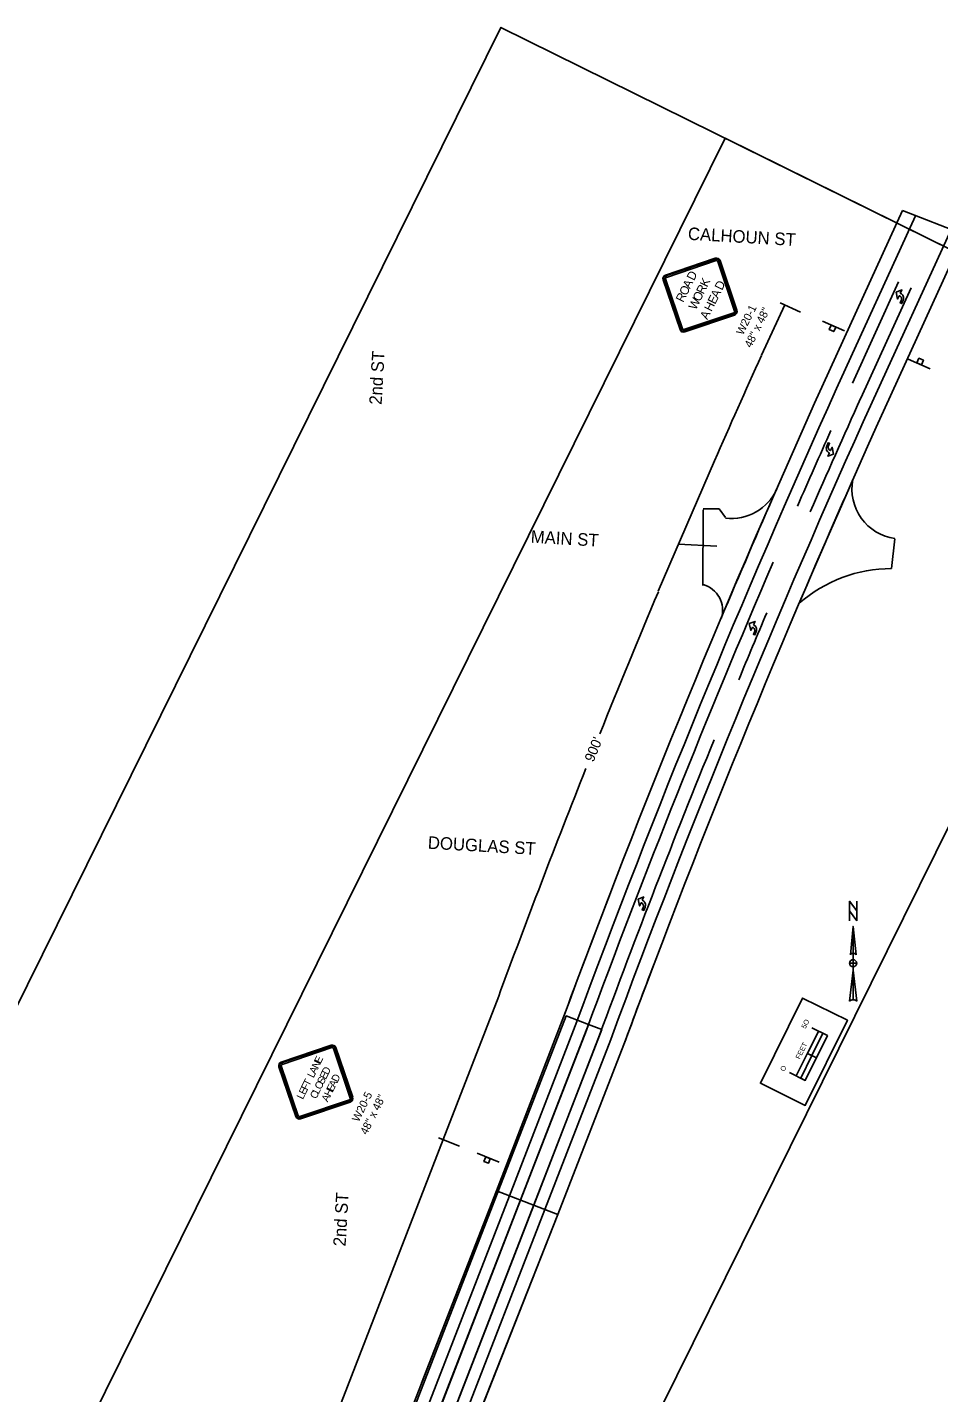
# Model space of a CAD drawing. Extents: x 14104283 to 14128447, y 8633203 to 8671666.
# Drawn here: x 14119504 to 14120414, y 8670301 to 8671666 of the extents above; entities that cross this region are included whole.
import ezdxf

# ---------------------------------------------------------------- set-up
doc = ezdxf.new("R2010")
doc.units = 0
for name, color, linetype in [('Cell', 7, 'Continuous'), ('Default', 7, 'Continuous'), ('dsnCellsNorthArrow', 7, 'Continuous'), ('dsnCellsScaleBlock', 7, 'Continuous'), ('dsnNonPlotable', 7, 'Continuous'), ('dsnPaintExistingBrokenLaneLineWhite', 7, 'Continuous'), ('dsnPaintExistingDoubleCenterYellow', 7, 'Continuous'), ('dsnPaintExistingEdgeLineRightWhite', 7, 'Continuous'), ('dsnPaintExistingLaneLineWhite', 7, 'Continuous'), ('dsnPaintExistingNoPassingYellow', 7, 'Continuous'), ('dsnShadingPaved', 7, 'Continuous'), ('dsnStdLabel', 7, 'Continuous'), ('dsnTextOverlapEven', 7, 'Continuous'), ('dsnTextOverlapOdd', 7, 'Continuous')]:
    doc.layers.add(name, color=color, linetype=linetype)

msp = doc.modelspace()

# ---------------------------------------------------------------- linework, layer by layer
at = {"layer": 'Cell'}
for p, q in [((14120190.9, 8671434.9), (14120141.2, 8671418.1)), ((14120191.2, 8671434), (14120191.7, 8671432.6)), ((14120193.3, 8671431.8), (14120194.8, 8671432.3)), ((14120212.5, 8671382.9), (14120195.7, 8671432.6)), ((14120142, 8671415.7), (14120141.5, 8671417.2)), ((14120138.8, 8671413.4), (14120155.7, 8671363.6)), ((14120139.7, 8671413.7), (14120141.2, 8671414.2)), ((14120374.9, 8671397.3), (14120374.6, 8671397.4)), ((14120375.7, 8671399.8), (14120375.9, 8671399.7)), ((14120160.4, 8671361.3), (14120210.1, 8671378.1)), ((14120209.3, 8671380.5), (14120209.8, 8671379)), ((14120211.6, 8671382.6), (14120210.1, 8671382.1)), ((14120158, 8671364.4), (14120156.5, 8671363.9)), ((14120160.1, 8671362.2), (14120159.6, 8671363.6)), ((14120298.1, 8671372), (14120320.1, 8671362.2)), ((14120405.4, 8671324.5), (14120383.4, 8671334.2)), ((14120305, 8671240.3), (14120304.8, 8671240.4)), ((14120305.8, 8671242.8), (14120306.1, 8671242.7)), ((14120228.2, 8671066.1), (14120227.9, 8671066.2)), ((14120229, 8671068.6), (14120229.2, 8671068.5)), ((14120117.1, 8670790.7), (14120116.9, 8670790.8)), ((14120118, 8670793.2), (14120118.1, 8670793.1)), ((14119807.1, 8670648.4), (14119757.4, 8670631.5)), ((14119807.4, 8670647.5), (14119807.9, 8670646)), ((14119809.5, 8670645.2), (14119811, 8670645.7)), ((14119828.7, 8670596.3), (14119811.9, 8670646)), ((14119755, 8670626.8), (14119771.8, 8670577.1)), ((14119755.9, 8670627.1), (14119757.4, 8670627.6)), ((14119758.2, 8670629.2), (14119757.7, 8670630.7)), ((14119776.6, 8670574.7), (14119826.3, 8670591.5)), ((14119825.5, 8670593.9), (14119826, 8670592.4)), ((14119827.8, 8670596), (14119826.3, 8670595.5)), ((14119774.2, 8670577.9), (14119772.7, 8670577.4)), ((14119776.3, 8670575.6), (14119775.8, 8670577.1)), ((14119952.9, 8670540.4), (14119975.1, 8670531.4))]:
    msp.add_line(p, q, dxfattribs=at)
for points in [[(14120191.2, 8671434), (14120141.5, 8671417.2), (14120142, 8671415.7), (14120191.7, 8671432.6), (14120191.2, 8671434)], [(14120211.6, 8671382.6), (14120194.8, 8671432.3), (14120193.3, 8671431.8), (14120210.1, 8671382.1), (14120211.6, 8671382.6)], [(14120139.7, 8671413.7), (14120156.5, 8671363.9), (14120158, 8671364.4), (14120141.2, 8671414.2), (14120139.7, 8671413.7)], [(14120160.1, 8671362.2), (14120209.8, 8671379), (14120209.3, 8671380.5), (14120159.6, 8671363.6), (14120160.1, 8671362.2)], [(14120311.2, 8671366.1), (14120306.7, 8671368.1), (14120304.7, 8671363.6), (14120309.2, 8671361.6)], [(14120392.3, 8671330.4), (14120396.8, 8671328.4), (14120398.7, 8671332.9), (14120394.3, 8671334.9)], [(14119807.4, 8670647.5), (14119757.7, 8670630.7), (14119758.2, 8670629.2), (14119807.9, 8670646), (14119807.4, 8670647.5)], [(14119827.8, 8670596), (14119811, 8670645.7), (14119809.5, 8670645.2), (14119826.3, 8670595.5), (14119827.8, 8670596)], [(14119755.9, 8670627.1), (14119772.7, 8670577.4), (14119774.2, 8670577.9), (14119757.4, 8670627.6), (14119755.9, 8670627.1)], [(14119776.3, 8670575.6), (14119826, 8670592.4), (14119825.5, 8670593.9), (14119775.8, 8670577.1), (14119776.3, 8670575.6)], [(14119966.1, 8670534.9), (14119961.6, 8670536.7), (14119959.8, 8670532.2), (14119964.3, 8670530.4)]]:
    msp.add_lwpolyline(points, close=True, dxfattribs=at)
for points in [[(14120371.5, 8671401), (14120377.3, 8671403.2), (14120375.7, 8671399.8)], [(14120371.5, 8671401), (14120377.3, 8671403.2), (14120375.7, 8671399.8)], [(14120374.6, 8671397.4), (14120373, 8671394.1), (14120371.5, 8671401)], [(14120374.6, 8671397.4), (14120373, 8671394.1), (14120371.5, 8671401)], [(14120374.9, 8671397.3), (14120374.6, 8671397.4)], [(14120375.7, 8671399.8), (14120375.9, 8671399.7)], [(14120378.5, 8671393), (14120377.1, 8671389.6), (14120375.7, 8671390.2), (14120376.7, 8671392.6)], [(14120378.5, 8671393), (14120377.1, 8671389.6), (14120375.7, 8671390.2), (14120376.7, 8671392.6)], [(14120311.2, 8671366.1), (14120306.7, 8671368.1), (14120304.7, 8671363.6), (14120309.2, 8671361.6), (14120311.2, 8671366.1)], [(14120392.3, 8671330.4), (14120396.8, 8671328.4), (14120398.7, 8671332.9), (14120394.3, 8671334.9), (14120392.3, 8671330.4)], [(14120302.2, 8671247.1), (14120303.6, 8671250.5), (14120305, 8671250), (14120304, 8671247.5)], [(14120302.2, 8671247.1), (14120303.6, 8671250.5), (14120305, 8671250), (14120304, 8671247.5)], [(14120309.1, 8671239.2), (14120303.4, 8671237), (14120305, 8671240.3)], [(14120309.1, 8671239.2), (14120303.4, 8671237), (14120305, 8671240.3)], [(14120305, 8671240.3), (14120304.8, 8671240.4)], [(14120305.8, 8671242.8), (14120306.1, 8671242.7)], [(14120306.1, 8671242.7), (14120307.7, 8671246), (14120309.1, 8671239.2)], [(14120306.1, 8671242.7), (14120307.7, 8671246), (14120309.1, 8671239.2)], [(14120224.8, 8671069.7), (14120230.6, 8671071.9), (14120229, 8671068.6)], [(14120224.8, 8671069.7), (14120230.6, 8671071.9), (14120229, 8671068.6)], [(14120227.9, 8671066.2), (14120226.3, 8671062.9), (14120224.8, 8671069.7)], [(14120227.9, 8671066.2), (14120226.3, 8671062.9), (14120224.8, 8671069.7)], [(14120228.2, 8671066.1), (14120227.9, 8671066.2)], [(14120229, 8671068.6), (14120229.2, 8671068.5)], [(14120231.8, 8671061.8), (14120230.4, 8671058.4), (14120229, 8671058.9), (14120230, 8671061.4)], [(14120231.8, 8671061.8), (14120230.4, 8671058.4), (14120229, 8671058.9), (14120230, 8671061.4)], [(14120113.8, 8670794.4), (14120119.5, 8670796.6), (14120118, 8670793.2)], [(14120113.8, 8670794.4), (14120119.5, 8670796.6), (14120118, 8670793.2)], [(14120116.9, 8670790.8), (14120115.3, 8670787.5), (14120113.8, 8670794.4)], [(14120116.9, 8670790.8), (14120115.3, 8670787.5), (14120113.8, 8670794.4)], [(14120117.1, 8670790.7), (14120116.9, 8670790.8)], [(14120118, 8670793.2), (14120118.1, 8670793.1)], [(14120120.8, 8670786.4), (14120119.4, 8670783), (14120118, 8670783.6), (14120119, 8670786)], [(14120120.8, 8670786.4), (14120119.4, 8670783), (14120118, 8670783.6), (14120119, 8670786)], [(14119966.1, 8670534.9), (14119961.6, 8670536.7), (14119959.8, 8670532.2), (14119964.3, 8670530.4), (14119966.1, 8670534.9)]]:
    msp.add_lwpolyline(points, dxfattribs=at)
for centre, radius, start, end in [((14120192.1, 8671431.4), 3.75, 18.6913, 108.691), ((14120192.1, 8671431.4), 2.81, 18.6913, 108.691), ((14120192.1, 8671431.4), 1.25, 18.6913, 108.691), ((14120142.4, 8671414.6), 3.75, 108.6912, 198.6909), ((14120142.4, 8671414.6), 2.81, 108.6912, 198.6909), ((14120142.4, 8671414.6), 1.25, 108.6912, 198.6909), ((14120208.9, 8671381.7), 1.25, 288.6911, 18.6913), ((14120208.9, 8671381.7), 2.81, 288.6911, 18.6913), ((14120208.9, 8671381.7), 3.75, 288.6911, 18.6913), ((14120159.2, 8671364.8), 3.75, 198.6909, 288.6911), ((14120159.2, 8671364.8), 2.81, 198.6909, 288.6911), ((14120159.2, 8671364.8), 1.25, 198.6909, 288.6911), ((14119808.3, 8670644.8), 3.75, 18.6913, 108.691), ((14119808.3, 8670644.8), 2.81, 18.6913, 108.691), ((14119808.3, 8670644.8), 1.25, 18.6913, 108.691), ((14119758.6, 8670628), 3.75, 108.6912, 198.6909), ((14119758.6, 8670628), 2.81, 108.6912, 198.6909), ((14119758.6, 8670628), 1.25, 108.6912, 198.6909), ((14119825.1, 8670595.1), 1.25, 288.6911, 18.6913), ((14119825.1, 8670595.1), 2.81, 288.6911, 18.6913), ((14119825.1, 8670595.1), 3.75, 288.6911, 18.6913), ((14119775.4, 8670578.3), 3.75, 198.6909, 288.6911), ((14119775.4, 8670578.3), 2.81, 198.6909, 288.6911), ((14119775.4, 8670578.3), 1.25, 198.6909, 288.6911)]:
    msp.add_arc(centre, radius, start, end, dxfattribs=at)
for centre, major_axis in [((14120373.5, 8671393.9), (-1.4, -3.4)), ((14120373.5, 8671393.9), (-1.4, -3.4)), ((14120373.9, 8671394.9), (-2, -4.86)), ((14120373.9, 8671394.9), (-2, -4.86)), ((14120306.8, 8671245.2), (2, 4.86)), ((14120306.8, 8671245.2), (2, 4.86)), ((14120307.2, 8671246.2), (1.4, 3.4)), ((14120307.2, 8671246.2), (1.4, 3.4)), ((14120226.8, 8671062.7), (-1.4, -3.4)), ((14120226.8, 8671062.7), (-1.4, -3.4)), ((14120227.2, 8671063.6), (-2, -4.86)), ((14120227.2, 8671063.6), (-2, -4.86)), ((14120115.7, 8670787.3), (-1.4, -3.4)), ((14120115.7, 8670787.3), (-1.4, -3.4)), ((14120116.1, 8670788.3), (-2, -4.86)), ((14120116.1, 8670788.3), (-2, -4.86))]:
    msp.add_ellipse(centre, major_axis=major_axis, ratio=0.9474, start_param=1.570796, end_param=3.141593, dxfattribs=at)
at = {"layer": 'Default'}
for p, q in [((14120299, 8671309.7), (14120377.9, 8671482.5)), ((14120377.9, 8671482.5), (14120439.4, 8671458.6)), ((14120439.4, 8671458.6), (14120360.6, 8671285.8)), ((14120194.8, 8671184.3), (14120178.7, 8671184.3)), ((14120194.8, 8671184.3), (14120178.7, 8671184.3)), ((14120201.1, 8671175.8), (14120194.8, 8671184.3)), ((14120201.1, 8671175.8), (14120194.8, 8671184.3)), ((14120178.7, 8671183.5), (14120178.6, 8671107.9)), ((14120178.7, 8671183.5), (14120178.6, 8671107.9)), ((14120370.3, 8671154.6), (14120366.9, 8671124.9)), ((14120370.3, 8671154.6), (14120366.9, 8671124.9)), ((14119972.2, 8670502.9), (14120038.1, 8670672.9)), ((14120099.6, 8670649), (14120033.7, 8670479.1)), ((14120033.7, 8670479.1), (14119972.2, 8670502.9))]:
    msp.add_line(p, q, dxfattribs=at)
msp.add_lwpolyline([(14119861.3, 8670216.9), (14119921, 8670193.8), (14120033.7, 8670479.1), (14119972.2, 8670502.9)], close=True, dxfattribs=at)
for centre, radius, start, end in [((14129121.8, 8667322.2), 9682.1, 155.67905, 159.75253), ((14129183.4, 8667298.3), 9682.1, 155.67905, 159.75253), ((14129183.4, 8667298.3), 9682.1, 156.14717, 156.94403), ((14129183.4, 8667298.3), 9682.1, 156.14717, 156.94403), ((14120377.6, 8671204.3), 50.2, 169.2669, 261.6204), ((14120377.6, 8671204.3), 50.2, 169.2669, 261.6204), ((14129121.8, 8667321.8), 9682.1, 156.35706, 157.19061), ((14129121.8, 8667321.8), 9682.1, 156.35706, 157.19061), ((14120206.8, 8671224.6), 49.9, 263.4387, 336.3571), ((14120206.8, 8671224.6), 49.9, 263.4387, 336.3571), ((14120367.2, 8670984.5), 140.3, 90.1123, 131.2245), ((14120367.2, 8670984.5), 140.3, 90.1123, 131.2245), ((14120171.7, 8671083.2), 26.5, 342.4439, 74.5077), ((14120171.7, 8671083.2), 26.5, 342.4439, 74.5077)]:
    msp.add_arc(centre, radius, start, end, dxfattribs=at)
at = {"layer": 'dsnCellsNorthArrow'}
for p, q in [((14120328.6, 8670767), (14120331.5, 8670738.8)), ((14120328.6, 8670767), (14120328.6, 8670693.7)), ((14120325.8, 8670738.8), (14120325.8, 8670738.8)), ((14120325.9, 8670739), (14120326.5, 8670739.6)), ((14120325.1, 8670692.3), (14120328.6, 8670723.3)), ((14120328.6, 8670726.8), (14120328.6, 8670726.8))]:
    msp.add_line(p, q, dxfattribs=at)
msp.add_lwpolyline([(14120332.2, 8670772.6), (14120325.1, 8670782.5), (14120325.1, 8670792.3), (14120332.2, 8670782.5)], close=True, dxfattribs=at)
for points in [[(14120325.1, 8670772.6), (14120325.1, 8670792.3), (14120332.2, 8670782.5), (14120332.2, 8670792.3)], [(14120325.8, 8670738.8), (14120328.6, 8670767), (14120328.6, 8670740.2)], [(14120332.2, 8670730.3), (14120328.6, 8670730.3), (14120328.6, 8670733.9)], [(14120328.6, 8670726.8), (14120328.6, 8670730.3), (14120325.1, 8670730.3)], [(14120328.6, 8670693.7), (14120328.6, 8670723.3), (14120332.2, 8670692.3)]]:
    msp.add_lwpolyline(points, dxfattribs=at)
for centre, radius, start, end in [((14120328.6, 8670730.3), 3.52, 90, 180), ((14120328.6, 8670736.7), 3.52, 90.0204, 143.1257), ((14120328.6, 8670736.7), 3.52, 36.8481, 90.0218), ((14120328.6, 8670730.3), 3.52, 0, 90), ((14120328.6, 8670730.3), 3.52, 180, 270), ((14120328.6, 8670730.3), 3.52, 270, 360), ((14120328.6, 8670688.6), 5.1, 89.9894, 133.619), ((14120328.6, 8670688.6), 5.11, 46.4021, 90.0006)]:
    msp.add_arc(centre, radius, start, end, dxfattribs=at)
at = {"layer": 'dsnCellsScaleBlock'}
msp.add_line((14120291.9, 8670635.6), (14120282.9, 8670640.1), dxfattribs=at)
msp.add_line((14120291.9, 8670635.6), (14120282.9, 8670640.1), dxfattribs=at)
for points in [[(14120235.9, 8670610.3), (14120278, 8670695.5), (14120322.8, 8670673.3), (14120280.7, 8670588.2)], [(14120280.7, 8670588.2), (14120235.9, 8670610.3), (14120278, 8670695.5), (14120322.8, 8670673.3)], [(14120287.4, 8670637.9), (14120298.4, 8670660.3), (14120294, 8670662.5), (14120282.9, 8670640.1)], [(14120280.8, 8670613.2), (14120291.9, 8670635.6), (14120287.4, 8670637.9), (14120276.3, 8670615.4)]]:
    msp.add_lwpolyline(points, close=True, dxfattribs=at)
for points in [[(14120265.1, 8670621), (14120280.8, 8670613.2), (14120302.9, 8670658), (14120287.3, 8670665.8)], [(14120271.8, 8670617.6), (14120294, 8670662.5)]]:
    msp.add_lwpolyline(points, dxfattribs=at)
at = {"layer": 'dsnNonPlotable'}
for points in [[(14119282, 8670260.6), (14119976.8, 8671665.7), (14120882.2, 8671218.1), (14120187.4, 8669813)], [(14119506.2, 8670149.8), (14120200.9, 8671554.9), (14120653.6, 8671331.1), (14119958.8, 8669926)]]:
    msp.add_lwpolyline(points, close=True, dxfattribs=at)
at = {"layer": 'dsnPaintExistingBrokenLaneLineWhite'}
for p, q in [((14120312.1, 8671304.6), (14120390.9, 8671477.4)), ((14120347.5, 8671290.9), (14120426.4, 8671463.7)), ((14119985.2, 8670497.9), (14120051.1, 8670667.8)), ((14120020.7, 8670484.1), (14120086.6, 8670654.1)), ((14119874.4, 8670211.9), (14119985.2, 8670497.9)), ((14119909.8, 8670198.2), (14120020.7, 8670484.1))]:
    msp.add_line(p, q, dxfattribs=at)
for centre in [(14129134.9, 8667317.1), (14129170.3, 8667303.4)]:
    msp.add_arc(centre, 9682.1, 155.67905, 159.75253, dxfattribs=at)
at = {"layer": 'dsnPaintExistingDoubleCenterYellow'}
msp.add_line((14120154.2, 8671149.1), (14120192.4, 8671147.3), dxfattribs=at)
at = {"layer": 'dsnPaintExistingEdgeLineRightWhite'}
for p, q in [((14120038.1, 8670672.9), (14119972.2, 8670502.9)), ((14120033.7, 8670479.1), (14120099.6, 8670649)), ((14119972.2, 8670502.9), (14119897.5, 8670310.4)), ((14119921, 8670193.8), (14120033.7, 8670479.1))]:
    msp.add_line(p, q, dxfattribs=at)
for centre, start in [((14129121.8, 8667322.2), 158.95507), ((14129183.4, 8667298.3), 159.24373)]:
    msp.add_arc(centre, 9682.1, start, 159.75253, dxfattribs=at)
at = {"layer": 'dsnPaintExistingLaneLineWhite'}
for centre, start, end in [((14129146.1, 8667312.8), 155.92282, 156.41213), ((14129159.1, 8667307.7), 157.06665, 157.496)]:
    msp.add_arc(centre, 9682.1, start, end, dxfattribs=at)
at = {"layer": 'dsnPaintExistingNoPassingYellow'}
for p, q in [((14120373.9, 8671411.3), (14120327.8, 8671310.2)), ((14120336.3, 8671295.2), (14120386.6, 8671405.5)), ((14120062.3, 8670663.5), (14119996.4, 8670493.5)), ((14120009.5, 8670488.5), (14120075.4, 8670658.4)), ((14119996.4, 8670493.5), (14119885.6, 8670207.6)), ((14119898.7, 8670202.6), (14120009.5, 8670488.5))]:
    msp.add_line(p, q, dxfattribs=at)
for centre, start, end in [((14129159.1, 8667307.7), 155.67905, 156.4156), ((14129146.1, 8667312.8), 156.77428, 159.75253), ((14129159.1, 8667307.7), 157.87848, 159.75253)]:
    msp.add_arc(centre, 9682.1, start, end, dxfattribs=at)
at = {"layer": 'dsnShadingPaved'}
for points in [[(14119863.2, 8670216.3), (14120042.1, 8670677.7), (14120064.4, 8670669), (14119885.6, 8670207.6)], [(14119885.6, 8670207.6), (14120064.4, 8670669), (14120077.5, 8670663.9), (14119922.7, 8670264.6), (14119945.1, 8670255.9), (14119945.1, 8670255.9), (14119921, 8670193.9)]]:
    msp.add_lwpolyline(points, dxfattribs=at)
at = {"layer": 'dsnStdLabel'}
for p, q in [((14120260.2, 8671388.4), (14120237.2, 8671337.9)), ((14120276.1, 8671381.1), (14120255.6, 8671390.4)), ((14120133.7, 8671102.1), (14120190.2, 8671232.3)), ((14119919, 8670554), (14119974.7, 8670697.5)), ((14119908.8, 8670527.5), (14119919, 8670554)), ((14119914.4, 8670555.8), (14119935.3, 8670547.6)), ((14119807.7, 8670266.8), (14119908.8, 8670527.5))]:
    msp.add_line(p, q, dxfattribs=at)
for start, end in [(155.67905, 156.35706), (157.19273, 158.09638), (158.31519, 159.75253)]:
    msp.add_arc((14129121.8, 8667322.2), 9750.1, start, end, dxfattribs=at)

# ---------------------------------------------------------------- texts
at = {"layer": 'Cell'}
for s, height, p in [('D', 8.75, (14120169.6, 8671411.9)), ('K', 8.75, (14120182.8, 8671405.4)), ('O', 8.75, (14120162.2, 8671396.9)), ('A', 8.75, (14120165.6, 8671403.9)), ('R', 8.75, (14120179.2, 8671398.3)), ('A', 8.75, (14120193.6, 8671394.1)), ('D', 8.75, (14120197.6, 8671402.3)), ('R', 8.75, (14120158.8, 8671390.2)), ('W', 8.75, (14120171.5, 8671382.6)), ('O', 8.75, (14120175.6, 8671391)), ('H', 8.75, (14120187.1, 8671381)), ('E', 8.75, (14120190.7, 8671388.3)), ('A', 8.75, (14120183, 8671372.9)), ('W20-1', 8, (14120218.5, 8671357.5)), ('48" x 48"', 8, (14120226.7, 8671344.8)), ('E', 7.5, (14119796.6, 8670629.3)), ('A', 7.5, (14119791.5, 8670618.9)), ('N', 7.5, (14119794.1, 8670624.2)), ('D', 7.5, (14119804.1, 8670618.1)), ('F', 7.5, (14119783.4, 8670602.6)), ('T', 7.5, (14119785.4, 8670606.7)), ('L', 7.5, (14119789.6, 8670615.1)), ('O', 7.5, (14119796.9, 8670603.4)), ('S', 7.5, (14119799.4, 8670608.5)), ('E', 7.5, (14119801.9, 8670613.6)), ('A', 7.5, (14119811, 8670605.5)), ('D', 7.5, (14119813.6, 8670610.8)), ('L', 7.5, (14119779, 8670593.6)), ('E', 7.5, (14119781.2, 8670598.1)), ('C', 7.5, (14119792.3, 8670594.1)), ('L', 7.5, (14119794.7, 8670599)), ('A', 7.5, (14119803.8, 8670591)), ('H', 7.5, (14119806.5, 8670596.3)), ('E', 7.5, (14119809, 8670601.4)), ('W20-5', 8, (14119834.7, 8670571)), ('48" x 48"', 8, (14119842.9, 8670558.2))]:
    msp.add_text(s, height=height, rotation=63.6912, dxfattribs=at).set_placement(p)
at = {"layer": 'dsnCellsScaleBlock'}
for s, p in [('5O', (14120281, 8670664.4)), ('FEET', (14120275.3, 8670633.8)), ('O', (14120259.9, 8670621.7))]:
    msp.add_text(s, height=5, rotation=63.6912, dxfattribs=at).set_placement(p)
at = {"layer": 'dsnStdLabel'}
msp.add_text("900'", height=10, rotation=67.6002, dxfattribs=at).set_placement((14120069.1, 8670930.7))
at = {"layer": 'dsnTextOverlapEven'}
for s, rotation, p in [('CALHOUN ST', 356.6912, (14120163.3, 8671453.4)), ('2nd ST', 86.6912, (14119857.6, 8671288.2)), ('MAIN ST', 356.6912, (14120006.3, 8671150.6)), ('2nd ST', 86.6912, (14119821.6, 8670447))]:
    msp.add_text(s, height=12.5, rotation=rotation, dxfattribs=at).set_placement(p)
at = {"layer": 'dsnTextOverlapOdd'}
msp.add_text('DOUGLAS ST', height=12.5, rotation=356.6912, dxfattribs=at).set_placement((14119903.5, 8670844.8))

doc.saveas('drawing.dxf')
